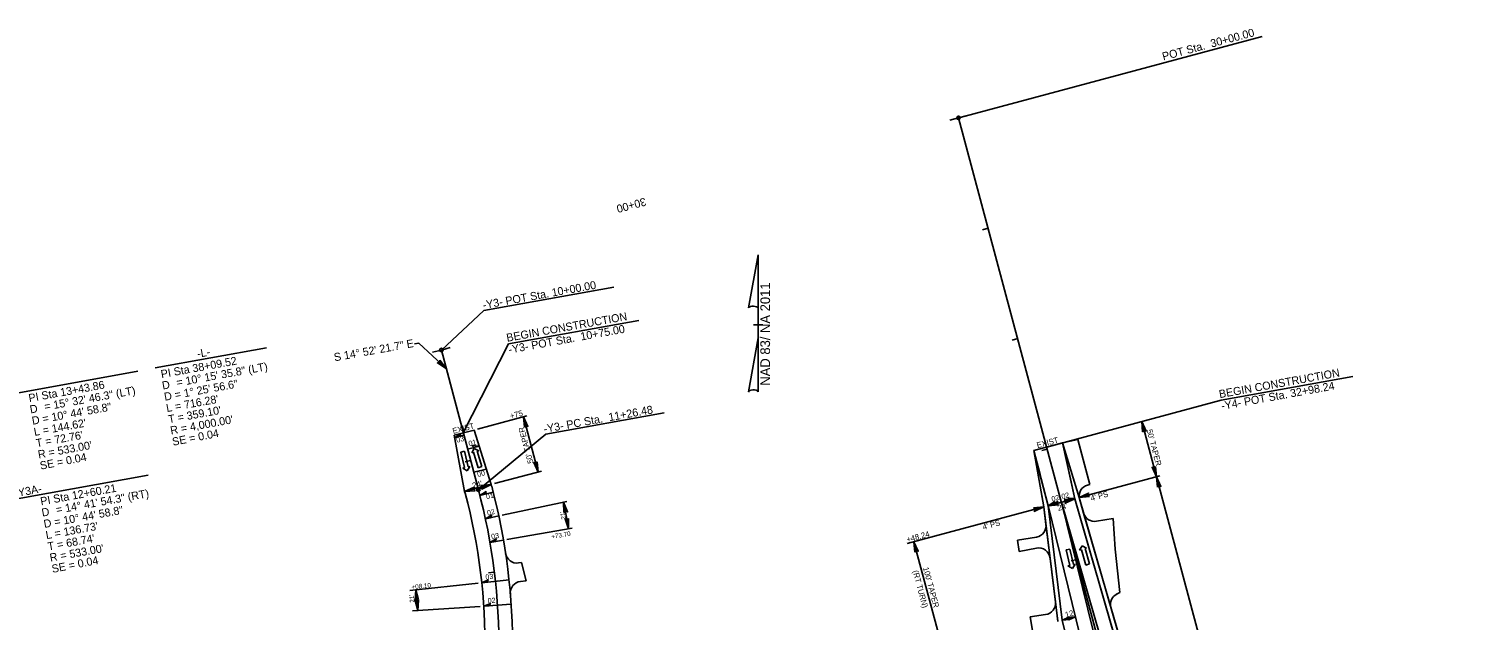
# Model space of a CAD drawing. Extents: x 1616561 to 1622460, y 896726 to 899651.
# Drawn here: x 1620474 to 1621727, y 898481 to 898999 of the extents above; entities that cross this region are included whole.
import ezdxf

# ---------------------------------------------------------------- set-up
doc = ezdxf.new("R2010")
doc.units = 0
for name, color, linetype in [('Old_Level_3', 7, 'Continuous'), ('Prop Dimension', 7, 'Continuous'), ('Prop Horizontal Alignment', 7, 'Continuous'), ('Prop Lane Arrow CELL', 7, 'Continuous'), ('Prop North Arrow NAD83 for Plan Sheets CELL', 7, 'Continuous'), ('Prop Shade Light', 7, 'Continuous'), ('Prop Superelevation  Arrow CELL', 7, 'Continuous'), ('Prop Superelevation Label', 7, 'Continuous'), ('Prop Terminator CELL', 7, 'Continuous'), ('Scratch_Level_1', 7, 'Continuous'), ('Sheet Cutting Line CELL', 7, 'Continuous'), ('Sheet North Arrow CELL', 7, 'Continuous'), ('Sheet Sticker Incomplete CELL', 7, 'Continuous'), ('Sheet Sticker Preliminary CELL', 7, 'Continuous')]:
    doc.layers.add(name, color=color, linetype=linetype)

msp = doc.modelspace()

# ---------------------------------------------------------------- linework, layer by layer
at = {"layer": 'Old_Level_3'}
for p, q in [((1621365.9, 898581.8), (1621437.8, 898290.2)), ((1621377.6, 898584.6), (1621449.4, 898293.3)), ((1621377.6, 898584.6), (1621461, 898296.4))]:
    msp.add_line(p, q, dxfattribs=at)
at = {"layer": 'Prop Dimension'}
for p, q in [((1620909.8, 898660.1), (1620866.5, 898648.6)), ((1620906.9, 898659.3), (1620919.7, 898611)), ((1621460.7, 898606.9), (1621447.8, 898655.2)), ((1620922.6, 898611.8), (1620881.5, 898600.9)), ((1621463.6, 898607.7), (1621393, 898588.8)), ((1621538.3, 898317.1), (1621460.7, 898606.9)), ((1620878.6, 898600.1), (1620855.4, 898593.9)), ((1621362.1, 898580.5), (1621242.6, 898548.5)), ((1621377.6, 898584.6), (1621366, 898581.5)), ((1621389.2, 898587.7), (1621377.6, 898584.6)), ((1621248.4, 898550), (1621274.3, 898453.4)), ((1621389.9, 898484.4), (1621378.3, 898481.3))]:
    msp.add_line(p, q, dxfattribs=at)
at = {"layer": 'Prop Horizontal Alignment'}
for p, q in [((1621353.4, 898629.9), (1621362.1, 898580.5)), ((1621393, 898588.8), (1621378.5, 898636.6)), ((1621362.1, 898580.5), (1621374.4, 898480.5)), ((1621393, 898588.8), (1621476.4, 898300.5))]:
    msp.add_line(p, q, dxfattribs=at)
at = {"layer": 'Prop Lane Arrow CELL'}
for p, q in [((1620852, 898628.5), (1620855.2, 898629.3)), ((1620855.2, 898614.9), (1620852, 898628.5)), ((1620855.2, 898629.3), (1620858.4, 898615.6)), ((1620861.7, 898627.8), (1620863.8, 898631.7)), ((1620863.1, 898628.3), (1620861.7, 898627.8)), ((1620867.1, 898614.8), (1620863.1, 898628.3)), ((1620863.8, 898631.7), (1620867.7, 898629.6)), ((1620867.7, 898629.6), (1620866.3, 898629.2)), ((1620866.3, 898629.2), (1620870.3, 898615.8)), ((1620853.7, 898614.5), (1620855.2, 898614.9)), ((1620857.6, 898612.2), (1620853.7, 898614.5)), ((1620859.9, 898616), (1620857.6, 898612.2)), ((1620858.4, 898615.6), (1620859.9, 898616)), ((1620870.3, 898615.8), (1620867.1, 898614.8)), ((1621381.6, 898543), (1621384.8, 898543.7)), ((1621384.8, 898529.3), (1621381.6, 898543)), ((1621384.8, 898543.7), (1621388, 898530.1)), ((1621393.5, 898542.7), (1621395.6, 898546.6)), ((1621395, 898543.1), (1621393.5, 898542.7)), ((1621399, 898529.7), (1621395, 898543.1)), ((1621395.6, 898546.6), (1621399.6, 898544.5)), ((1621399.6, 898544.5), (1621398.2, 898544.1)), ((1621398.2, 898544.1), (1621402.1, 898530.6)), ((1621383.3, 898529), (1621384.8, 898529.3)), ((1621387.2, 898526.7), (1621383.3, 898529)), ((1621389.5, 898530.4), (1621387.2, 898526.7)), ((1621388, 898530.1), (1621389.5, 898530.4)), ((1621402.1, 898530.6), (1621399, 898529.7))]:
    msp.add_line(p, q, dxfattribs=at)
at = {"layer": 'Prop North Arrow NAD83 for Plan Sheets CELL'}
for p, q in [((1621103.9, 898754.6), (1621112.1, 898801)), ((1621112.1, 898801), (1621112.1, 898801)), ((1621112.1, 898801), (1621112.1, 898801)), ((1621112.1, 898801), (1621112.1, 898753.2)), ((1621112.1, 898728.4), (1621112.1, 898754.6)), ((1621112.1, 898753.2), (1621112.1, 898754.5)), ((1621111.7, 898740), (1621108.1, 898740)), ((1621108.1, 898740), (1621108.1, 898740)), ((1621108.2, 898740), (1621116.2, 898740)), ((1621112.1, 898728.4), (1621103.8, 898681.1)), ((1621112.2, 898681.3), (1621112.1, 898728.4))]:
    msp.add_line(p, q, dxfattribs=at)
for points in [[(1620846.5, 898641.1), (1620851.8, 898644.6), (1620851, 898642.3)], [(1620868, 898633.8), (1620861.7, 898634.2), (1620863.5, 898632.6)], [(1620868.7, 898590.5), (1620874.1, 898593.9), (1620873.2, 898591.7)], [(1621366, 898581.5), (1621371.3, 898585), (1621370.5, 898582.7)], [(1621389.7, 898587.9), (1621383.4, 898588.2), (1621385.3, 898586.7)], [(1620873.5, 898570.1), (1620879, 898573.3), (1620878, 898571)], [(1620877.5, 898549.5), (1620883.1, 898552.5), (1620882.1, 898550.2)], [(1620870.3, 898514.1), (1620876.1, 898516.7), (1620874.9, 898514.6)], [(1620872.1, 898493.7), (1620878, 898496.1), (1620876.7, 898494)]]:
    msp.add_lwpolyline(points, close=True, dxfattribs=at)
for centre, start_param, end_param in [((1621108, 898754.2), 0.216388, 2.908219), ((1621108, 898681), 0.201328, 3.141593)]:
    msp.add_ellipse(centre, major_axis=(4.23, -0.03), ratio=0.461098, start_param=start_param, end_param=end_param, dxfattribs=at)
at = {"layer": 'Prop Shade Light'}
for p, q in [((1621353.4, 898629.9), (1621357.2, 898608.7)), ((1621358.9, 898609), (1621353.4, 898629.9)), ((1621393, 898588.8), (1621378.5, 898636.6)), ((1621357.2, 898608.7), (1621362.1, 898580.5)), ((1621366, 898581.5), (1621358.8, 898609.1)), ((1621378.3, 898481.3), (1621366, 898581.5)), ((1621423.9, 898296.4), (1621378.3, 898481.3))]:
    msp.add_line(p, q, dxfattribs=at)
for points in [[(1621378.5, 898636.6), (1621385.4, 898605.2), (1621389.2, 898587.7)], [(1621358.8, 898609.1), (1621357.2, 898608.7)], [(1621357.2, 898608.7), (1621358.9, 898609)], [(1621362.1, 898580.5), (1621364, 898565.2), (1621367.6, 898535.8), (1621372.4, 898497.4), (1621374.5, 898480.3)], [(1621389.2, 898587.7), (1621401.5, 898545), (1621472.6, 898299.5)], [(1621447.7, 898399.8), (1621431.8, 898454.7), (1621420.8, 898492.7), (1621397, 898575), (1621393, 898588.8)]]:
    msp.add_lwpolyline(points, dxfattribs=at)
at = {"layer": 'Prop Superelevation  Arrow CELL'}
for p, q in [((1621313.4, 898824.4), (1621308.6, 898823.1)), ((1621339.3, 898727.8), (1621334.4, 898726.5)), ((1621365.1, 898631.2), (1621360.3, 898629.9)), ((1620860.6, 898621.2), (1620855.8, 898619.9)), ((1621391, 898534.6), (1621386.1, 898533.3)), ((1620881.3, 898523.4), (1620876.4, 898522.8))]:
    msp.add_line(p, q, dxfattribs=at)
at = {"layer": 'Prop Superelevation Label'}
for p, q in [((1621287.6, 898921), (1621279.8, 898918.9)), ((1621287.6, 898921), (1621295.3, 898923.1)), ((1620835, 898717.8), (1620827.2, 898715.8)), ((1620835, 898717.8), (1620842.7, 898719.9))]:
    msp.add_line(p, q, dxfattribs=at)
at = {"layer": 'Prop Terminator CELL'}
for p, q in [((1620846.1, 898643.2), (1620863.6, 898647.8)), ((1620846.1, 898643.2), (1620855.4, 898593.9)), ((1620878.6, 898600.1), (1620863.6, 898647.8)), ((1621378.5, 898636.6), (1621391.9, 898639.6)), ((1621391.4, 898639.3), (1621391.9, 898639.6)), ((1621402.5, 898600.2), (1621391.9, 898639.6)), ((1621378.5, 898636.6), (1621353.4, 898629.9)), ((1621353.4, 898629.9), (1621366, 898581.5)), ((1621389.2, 898587.7), (1621378.5, 898636.6)), ((1620855.8, 898592.5), (1620855.4, 898593.9)), ((1620879, 898598.7), (1620878.6, 898600.1)), ((1621402.5, 898600.2), (1621400.5, 898599.7)), ((1621366, 898581.5), (1621378.3, 898481.3)), ((1621389.2, 898587.7), (1621472.6, 898299.5)), ((1621422.7, 898570.4), (1621408.3, 898568)), ((1621422.7, 898570.4), (1621424.5, 898543.6)), ((1621339.1, 898551.3), (1621355.8, 898554.1)), ((1621339.1, 898551.3), (1621340.6, 898541.4)), ((1621340.6, 898541.4), (1621355.7, 898544.4)), ((1621424.5, 898543.6), (1621428.7, 898505.7)), ((1620905, 898531.9), (1620902.4, 898531.5)), ((1620905, 898531.9), (1620909.3, 898515.8)), ((1620909.3, 898515.8), (1620904.3, 898515.3)), ((1621428.7, 898505.7), (1621425.9, 898504.3)), ((1621350.2, 898484.5), (1621363.7, 898486.3)), ((1621350.2, 898484.5), (1621352.3, 898472.5)), ((1621378.3, 898481.3), (1621423.9, 898296.4))]:
    msp.add_line(p, q, dxfattribs=at)
for points in [[(1620833.7, 898708.9), (1620839.3, 898701.6), (1620831.6, 898706.6), (1620833.5, 898707)], [(1620907.7, 898650.2), (1620906.9, 898659.3), (1620910.7, 898651), (1620908.9, 898651.7)], [(1621448.6, 898646.1), (1621447.8, 898655.2), (1621451.7, 898646.8), (1621449.9, 898647.5)], [(1620918.9, 898620.1), (1620919.7, 898611), (1620915.8, 898619.3), (1620917.7, 898618.6)], [(1621459.9, 898616), (1621460.7, 898606.9), (1621456.9, 898615.2), (1621458.7, 898614.5)], [(1621461.6, 898597.8), (1621460.7, 898606.9), (1621464.6, 898598.5), (1621462.8, 898599.2)], [(1620864.5, 898594.7), (1620855.4, 898593.9), (1620863.8, 898597.8), (1620863.1, 898596)], [(1620869.5, 898599.3), (1620878.6, 898600.1), (1620870.3, 898596.2), (1620871, 898598.1)], [(1621402.1, 898589.6), (1621393, 898588.8), (1621401.4, 898592.6), (1621400.7, 898590.8)], [(1620942.3, 898575.6), (1620941.9, 898584.7), (1620945.4, 898576.2), (1620943.5, 898577)], [(1621353, 898579.6), (1621362.1, 898580.5), (1621353.8, 898576.6), (1621354.5, 898578.4)], [(1621375.1, 898582.3), (1621366, 898581.5), (1621374.3, 898585.4), (1621373.6, 898583.6)], [(1621380.1, 898586.9), (1621389.2, 898587.7), (1621380.9, 898583.8), (1621381.6, 898585.7)], [(1620946.4, 898570.5), (1620946.4, 898561.4), (1620943.3, 898570), (1620945.1, 898569.1)], [(1621249.2, 898540.9), (1621248.4, 898550), (1621252.3, 898541.7), (1621250.4, 898542.4)], [(1620812, 898498.8), (1620812.6, 898508), (1620815.1, 898499.1), (1620813.4, 898500.1)], [(1620815.1, 898498.9), (1620814.5, 898489.8), (1620812, 898498.6), (1620813.7, 898497.7)], [(1621384.7, 898481.9), (1621378.3, 898481.3), (1621384.2, 898484), (1621383.7, 898482.7)], [(1621383.6, 898483.8), (1621389.9, 898484.4), (1621384.1, 898481.7), (1621384.6, 898483)]]:
    msp.add_lwpolyline(points, close=True, dxfattribs=at)
for centre, radius, start, end in [((1620352.3, 898458.8), 521, 359.3265, 14.8727), ((1620352.3, 898458.8), 545, 359.3265, 14.8727), ((1621403.1, 898590), 10, 104.985, 196.1308), ((1621354.1, 898564), 10, 279.7958, 7.0159), ((1621406.6, 898577.8), 10, 196.1308, 279.6455), ((1620901.1, 898541.4), 10, 188.5667, 277.5343), ((1621357.7, 898534.6), 10, 7.0159, 101.2871), ((1620905.3, 898505.3), 10, 95.8457, 184.8133), ((1621430.5, 898495.4), 10, 116.9154, 196.1308), ((1621362.4, 898496.2), 10, 277.4054, 7.0159)]:
    msp.add_arc(centre, radius, start, end, dxfattribs=at)
at = {"layer": 'Scratch_Level_1'}
for p, q in [((1620811.5, 898723.2), (1620815.4, 898723.9)), ((1620815.4, 898723.9), (1620839.3, 898701.6))]:
    msp.add_line(p, q, dxfattribs=at)
at = {"layer": 'Sheet Cutting Line CELL'}
for p, q in [((1621287.6, 898921), (1621727.5, 897277.4)), ((1620835, 898717.8), (1620867.4, 898595.6))]:
    msp.add_line(p, q, dxfattribs=at)
msp.add_arc((1620352.3, 898458.8), 533, 359.3265, 14.8727, dxfattribs=at)
at = {"layer": 'Sheet North Arrow CELL'}
for p, q in [((1621289, 898921.4), (1621553.2, 898992.1)), ((1620986, 898772.9), (1620872.2, 898752.3)), ((1620835, 898717.8), (1620872.2, 898752.3)), ((1620893.7, 898723.1), (1621007.7, 898743.7)), ((1620854.2, 898645.3), (1620893.7, 898723.1)), ((1621517.3, 898673.8), (1621632.5, 898694.6)), ((1621517.3, 898673.8), (1621364.7, 898632.9)), ((1621030, 898662.9), (1620926.4, 898644.2)), ((1620867.4, 898595.6), (1620926.4, 898644.2))]:
    msp.add_line(p, q, dxfattribs=at)
for centre in [(1621287.6, 898921), (1620835, 898717.8), (1620867.4, 898595.6)]:
    msp.add_circle(centre, 1.5, dxfattribs=at)
at = {"layer": 'Sheet Sticker Incomplete CELL'}
for p, q in [((1620584.7, 898702.1), (1620681.9, 898719.7)), ((1620360.7, 898661.6), (1620569.5, 898699.3)), ((1620377, 898571.9), (1620578.5, 898608.3))]:
    msp.add_line(p, q, dxfattribs=at)
at = {"layer": 'Sheet Sticker Preliminary CELL'}
for p, q in [((1620846.5, 898641.1), (1620854.7, 898643.3)), ((1620858, 898631.1), (1620868, 898633.8)), ((1620874.3, 898613.7), (1620863.4, 898610.8)), ((1620880.4, 898593.5), (1620868.7, 898590.5)), ((1620944.8, 898585.3), (1620888.2, 898573.2)), ((1621366, 898581.5), (1621389.9, 898587.9)), ((1620885.3, 898572.6), (1620873.5, 898570.1)), ((1620889.3, 898551.5), (1620877.5, 898549.5)), ((1620892.3, 898552), (1620949.4, 898561.9)), ((1620867.2, 898513.8), (1620807.5, 898507.4)), ((1620870.3, 898514.1), (1620894.2, 898516.7)), ((1620812.6, 898508), (1620814.5, 898489.8)), ((1620869.1, 898493.5), (1620809.9, 898489.5)), ((1620872.1, 898493.7), (1620896.1, 898495.3))]:
    msp.add_line(p, q, dxfattribs=at)
msp.add_arc((1620352.3, 898458.8), 602.9, 9.7968, 12.0543, dxfattribs=at)

# ---------------------------------------------------------------- texts
at = {"layer": 'Prop Dimension'}
for s, height, rotation, p in [('30+00', 7, 194.985, (1621013.1, 898851.2)), ('+75', 5, 14.8727, (1620895.8, 898657.5)), ('EXIST', 5, 14.8727, (1620845.5, 898644.4)), ("50' TAPER", 5, 104.8727, (1620915.7, 898619.2)), ('EXIST', 5, 15.0685, (1621356.7, 898631.9)), ("50' TAPER", 5, 284.985, (1621452, 898647.7)), ("24'", 5, 14.8727, (1620862.8, 898596.6)), ("4' PS", 5, 15.2232, (1621403.8, 898585.6)), ("24'", 5, 14.985, (1621374.9, 898577)), ("4' PS", 5, 15.2232, (1621309.3, 898560.4)), ('+48.24', 5, 14.985, (1621242.7, 898549.4)), ("100' TAPER", 5, 284.985, (1621256.4, 898527.2)), ('(RT TURN)', 5, 284.985, (1621247.4, 898524.4)), ("12'", 5, 14.985, (1621381.5, 898483.6))]:
    msp.add_text(s, height=height, rotation=rotation, dxfattribs=at).set_placement(p)
at = {"layer": 'Prop North Arrow NAD83 for Plan Sheets CELL'}
for s, height, rotation, p in [('NAD 83/ NA 2011', 8.5, 89.9808, (1621122.6, 898686.6)), ('02', 4.5, 14.9555, (1621369.5, 898585.1)), ('02', 4.5, 14.9555, (1621378.2, 898587.3))]:
    msp.add_text(s, height=height, rotation=rotation, dxfattribs=at).set_placement(p)
at = {"layer": 'Scratch_Level_1'}
msp.add_text('S 14%%d 52\' 21.7" E', height=7, rotation=10.2583, dxfattribs=at).set_placement((1620741.7, 898707.9))
at = {"layer": 'Sheet North Arrow CELL'}
for s, rotation, p in [('POT Sta.  30+00.00', 14.985, (1621466.8, 898971.1)), ('-Y3- POT Sta. 10+00.00', 10.2599, (1620871.8, 898753.6)), ('BEGIN CONSTRUCTION', 10.2599, (1620892.6, 898725)), ('-Y3- POT Sta.  10+75.00', 10.2599, (1620894.4, 898714.7)), ('BEGIN CONSTRUCTION', 10.2599, (1621516.1, 898675.7)), ('-Y4- POT Sta. 32+98.24', 10.2599, (1621518, 898665.4)), ('-Y3- PC Sta.  11+26.48', 10.2599, (1620925.1, 898645.2))]:
    msp.add_text(s, height=7, rotation=rotation, dxfattribs=at).set_placement(p)
at = {"layer": 'Sheet Sticker Incomplete CELL'}
for s, rotation, p in [('-L-', 10.2599, (1620621.9, 898711)), ('PI Sta 38+09.52', 10.2599, (1620590.2, 898693.2)), ('= 10%%d 15\' 35.8" (LT)', 10.2599, (1620603.9, 898685.8)), ('PI Sta 13+43.86', 10.2599, (1620474.5, 898672.2)), ('D', 10.2599, (1620591.3, 898683.2)), ('D = 1%%d 25\' 56.6"', 10.2599, (1620593.1, 898673.4)), ('= 15%%d 32\' 46.3" (LT)', 10.2599, (1620488.2, 898664.8)), ("L = 716.28'", 10.2599, (1620594.9, 898663.5)), ('D', 10.2599, (1620475.6, 898662.3)), ('D = 10%%d 44\' 58.8"', 10.2599, (1620477.4, 898652.4)), ("T = 359.10'", 10.2599, (1620596.7, 898653.7)), ("L = 144.62'", 10.2599, (1620479.1, 898642.6)), ("R = 4,000.00'", 10.2599, (1620598.5, 898643.9)), ("T = 72.76'", 10.2599, (1620480.9, 898632.8)), ('SE = 0.04', 11.0322, (1620600.2, 898634)), ("R = 533.00'", 10.2599, (1620482.7, 898622.9)), ('SE = 0.04', 11.0322, (1620484.5, 898613.1)), ('-Y3A-', 10.2599, (1620462.2, 898589)), ('PI Sta 12+60.21', 10.2599, (1620484.8, 898581.9)), ('= 14%%d 41\' 54.3" (RT)', 10.2599, (1620498.5, 898574.5)), ('D', 10.2599, (1620485.9, 898572)), ('D = 10%%d 44\' 58.8"', 10.2599, (1620487.7, 898562.1)), ("L = 136.73'", 10.2599, (1620489.5, 898552.3)), ("T = 68.74'", 10.2599, (1620491.2, 898542.4)), ("R = 533.00'", 10.2599, (1620493, 898532.6)), ('SE = 0.04', 11.0322, (1620494.8, 898522.8))]:
    msp.add_text(s, height=7, rotation=rotation, dxfattribs=at).set_placement(p)
at = {"layer": 'Sheet Sticker Preliminary CELL'}
for s, height, rotation, p in [('03', 4.5, 14.8727, (1620848.7, 898636.6)), ('01', 4.5, 14.8727, (1620859.4, 898633.6)), ('00', 4.5, 14.8727, (1620867, 898606.6)), ('01', 4.5, 14.3117, (1620874.6, 898587.2)), ('02', 4.5, 12.0543, (1620875.5, 898573)), ("21'", 4, 100.2599, (1620943.9, 898569.9)), ('03', 4.5, 9.7968, (1620879, 898552.3)), ('+73.70', 4, 9.7968, (1620931.6, 898552.5)), ('+08.10', 4, 6.0989, (1620809.1, 898508.4)), ('03', 4.5, 6.0989, (1620873.8, 898516.9)), ("21'", 4, 96.0989, (1620811.5, 898497)), ('02', 4.5, 3.8415, (1620875.7, 898496.2))]:
    msp.add_text(s, height=height, rotation=rotation, dxfattribs=at).set_placement(p)

doc.saveas('drawing.dxf')
